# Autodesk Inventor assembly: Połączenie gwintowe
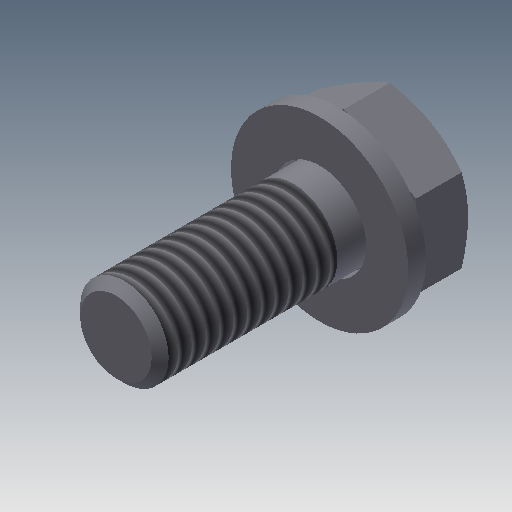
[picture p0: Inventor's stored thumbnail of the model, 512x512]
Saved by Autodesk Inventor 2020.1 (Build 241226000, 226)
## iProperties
Created: 2010-10
Part Number: Połączenie gwintowe
Document SubType Name: Assembly
Designer: F.Stasiak
ClientObjectVersion: 1
Manager: www.cadconsulting.pl
Company: Fabian Stasiak CAD Consulting
Author: F.Stasiak
Subject: Zbiór ćwiczeń. Autodesk Inventor 2020. Kurs podstawowy
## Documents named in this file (3)
- C:\2020_Kurs_podstawowy\R9 Zarządzanie plikami\369-000\Design Accelerator\Połączenie gwintowe5.iam
- C:\2020_Kurs_podstawowy\Zasoby\Content Center Files\pl-PL\ISO 7089\ISO 7089 - 8 - 140 HV(1).ipt
- C:\2020_Kurs_podstawowy\Zasoby\Content Center Files\pl-PL\ISO 4017(1)\ISO 4017 - M8 x 20ISO.ipt
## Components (2 placed, 2 different names)
1. ISO 7089 8 - 140 HV:1
2. ISO 4017 M8 x 20:1
